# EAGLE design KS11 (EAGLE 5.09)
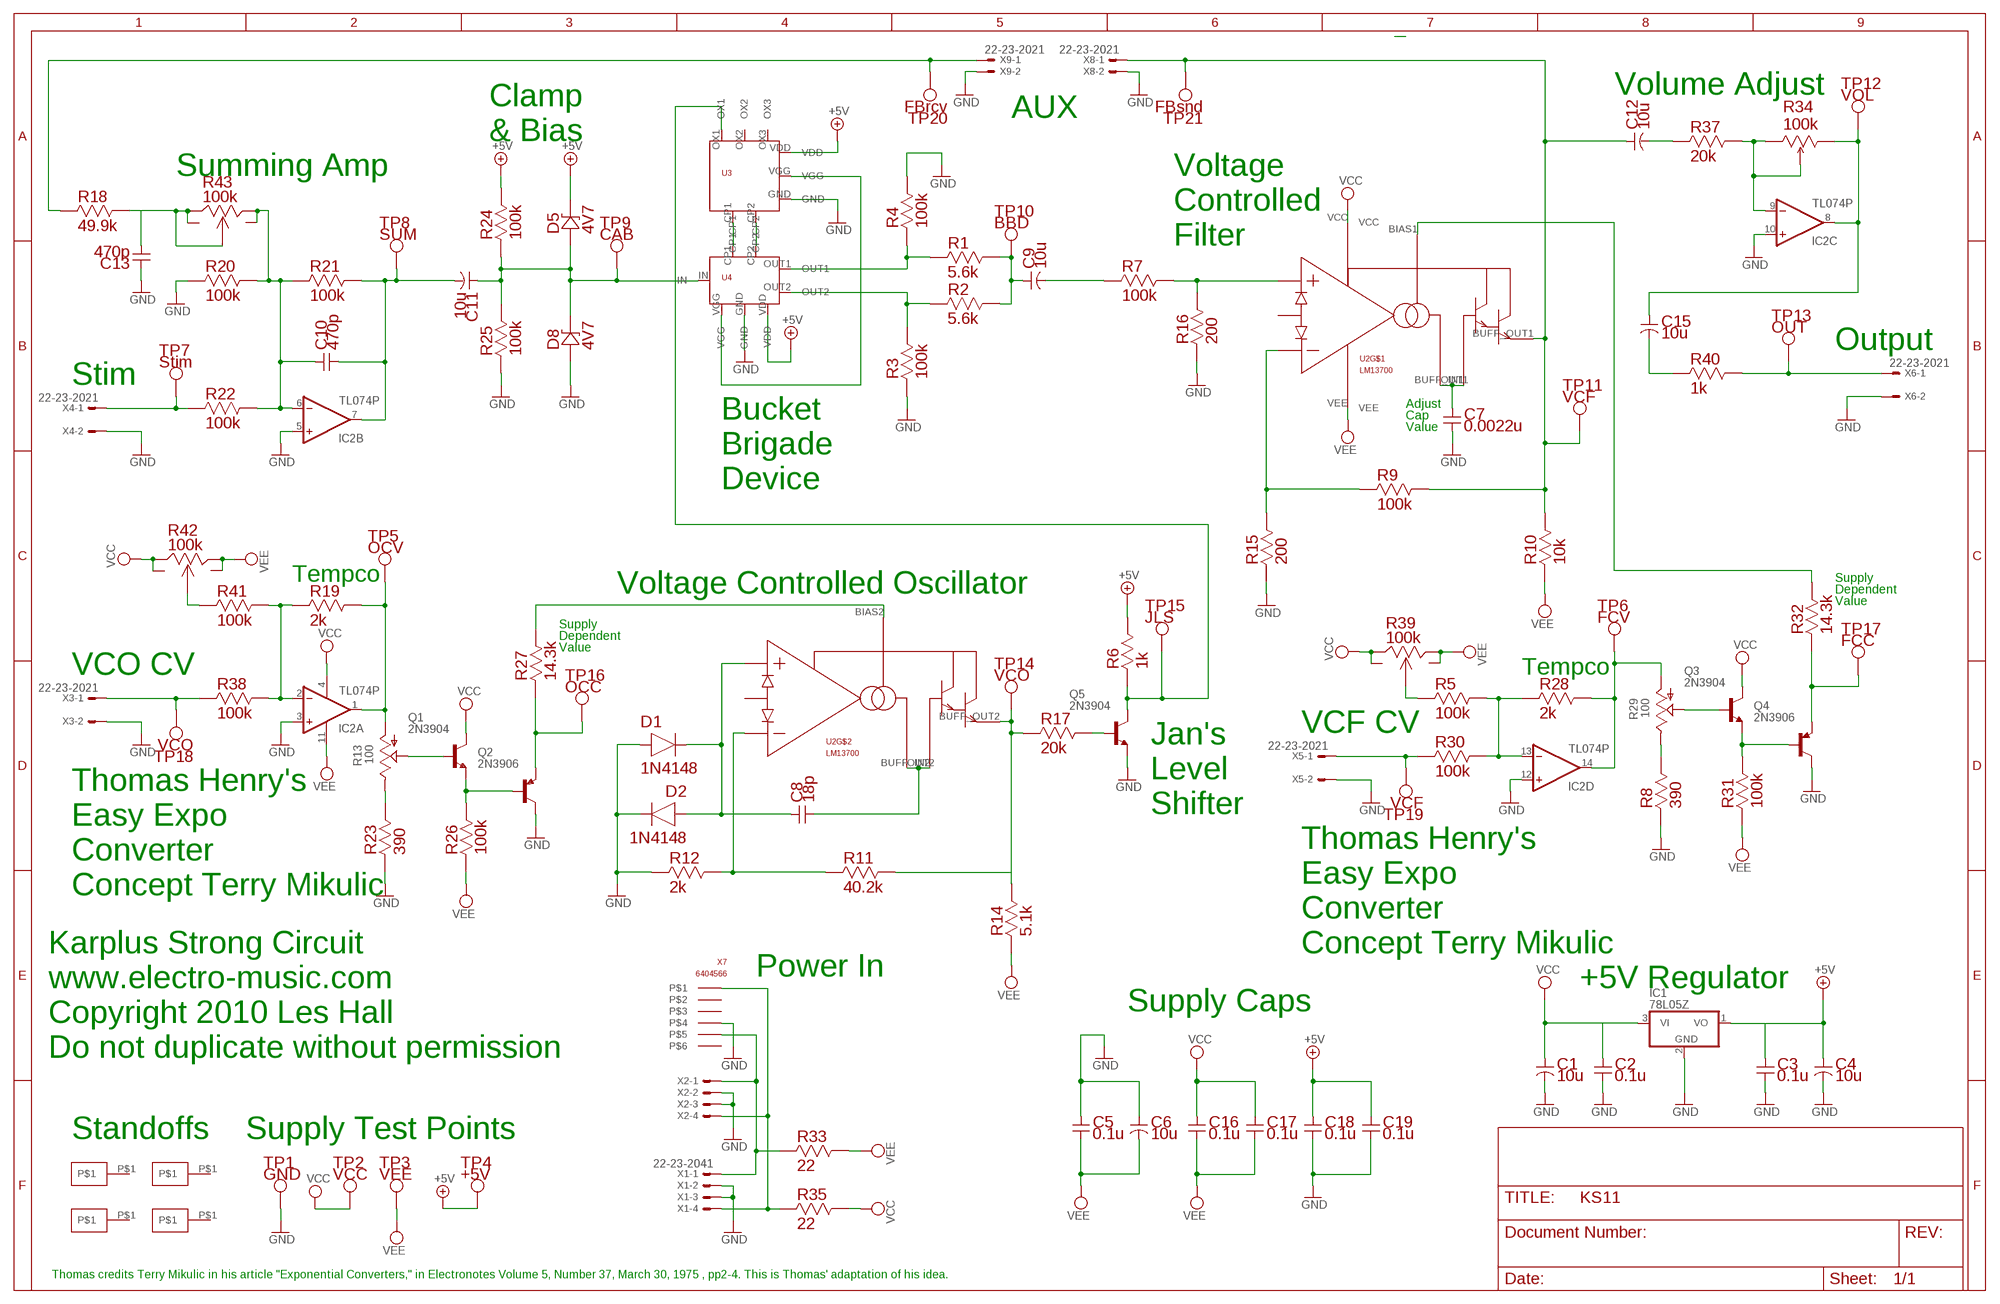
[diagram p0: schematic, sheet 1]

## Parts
C1  10u  ECAP100  [ECAP100]
C2  0.1u  CAP100  [CAP100]
C3  0.1u  CAP100  [CAP100]
C4  10u  ECAP100  [ECAP100]
C5  0.1u  CAP100  [CAP100]
C6  10u  ECAP100  [ECAP100]
C7  0.0022u  CAP100  [CAP100]
C8  18p  CAP100  [CAP100]
C9  10u  ECAP100  [ECAP100]
C10  470p  CAP100  [CAP100]
C11  10u  ECAP100  [ECAP100]
C12  10u  ECAP100  [ECAP100]
C13  470p  CAP100  [CAP100]
C15  10u  ECAP100  [ECAP100]
C16  0.1u  CAP100  [CAP100]
C17  0.1u  CAP100  [CAP100]
C18  0.1u  CAP100  [CAP100]
C19  0.1u  CAP100  [CAP100]
D1  1N4148  DIODE  [DIODE]
D2  1N4148  DIODE  [DIODE]
D5  4V7  ZENER  [ZENER]
D8  4V7  ZENER  [ZENER]
IC1  78L05Z  [TO92]
IC2  TL074P  [DIL14]
Q1  2N3904  [TO92]
Q2  2N3906  [TO92]
Q3  2N3904  [TO92]
Q4  2N3906  [TO92]
Q5  2N3904  [TO92]
R1  5.6k  RES400  [RES400]
R2  5.6k  RES400  [RES400]
R3  100k  RES400  [RES400]
R4  100k  RES400  [RES400]
R5  100k  RES400  [RES400]
R6  1k  RES400  [RES400]
R7  100k  RES400  [RES400]
R8  390  RES400  [RES400]
R9  100k  RES400  [RES400]
R10  10k  RES400  [RES400]
R11  40.2k  RES400  [RES400]
R12  2k  RES400  [RES400]
R13  100  TRIM_US-S64W  [S64W]
R14  5.1k  RES400  [RES400]
R15  200  RES400  [RES400]
R16  200  RES400  [RES400]
R17  20k  RES400  [RES400]
R18  49.9k  RES400  [RES400]
R19  2k  RES400  [RES400]
R20  100k  RES400  [RES400]
R21  100k  RES400  [RES400]
R22  100k  RES400  [RES400]
R23  390  RES400  [RES400]
R24  100k  RES400  [RES400]
R25  100k  RES400  [RES400]
R26  100k  RES400  [RES400]
R27  14.3k  RES400  [RES400]
R28  2k  RES400  [RES400]
R29  100  TRIM_US-S64W  [S64W]
R30  100k  RES400  [RES400]
R31  100k  RES400  [RES400]
R32  14.3k  RES400  [RES400]
R33  22  RES400  [RES400]
R34  100k  POTWHEEL  [POTWHEEL]
R35  22  RES400  [RES400]
R37  20k  RES400  [RES400]
R38  100k  RES400  [RES400]
R39  100k  POT2  [POT2]
R40  1k  RES400  [RES400]
R41  100k  RES400  [RES400]
R42  100k  POT2  [POT2]
R43  100k  POT2  [POT2]
S2  STANDOFF  [STANDOFF]
S3  STANDOFF  [STANDOFF]
S4  STANDOFF  [STANDOFF]
S5  STANDOFF  [STANDOFF]
TP1  GND  TESTPOINT  [TESTPOINT]
TP2  VCC  TESTPOINT  [TESTPOINT]
TP3  VEE  TESTPOINT  [TESTPOINT]
TP4  +5V  TESTPOINT  [TESTPOINT]
TP5  OCV  TESTPOINT  [TESTPOINT]
TP6  FCV  TESTPOINT  [TESTPOINT]
TP7  Stim  TESTPOINT  [TESTPOINT]
TP8  SUM  TESTPOINT  [TESTPOINT]
TP9  CAB  TESTPOINT  [TESTPOINT]
TP10  BBD  TESTPOINT  [TESTPOINT]
TP11  VCF  TESTPOINT  [TESTPOINT]
TP12  VOL  TESTPOINT  [TESTPOINT]
TP13  OUT  TESTPOINT  [TESTPOINT]
TP14  VCO  TESTPOINT  [TESTPOINT]
TP15  JLS  TESTPOINT  [TESTPOINT]
TP16  OCC  TESTPOINT  [TESTPOINT]
TP17  FCC  TESTPOINT  [TESTPOINT]
TP18  VCO  TESTPOINT  [TESTPOINT]
TP19  VCF  TESTPOINT  [TESTPOINT]
TP20  FBrcv  TESTPOINT  [TESTPOINT]
TP21  FBsnd  TESTPOINT  [TESTPOINT]
U2  LM13700  [LM13700]
U3  MN3102  [MN3102]
U4  MN3207  [MN3207]
X1  22-23-2041  [22-23-2041]
X2  KK-156-4  [KK-156-4]
X3  22-23-2021  [22-23-2021]
X4  22-23-2021  [22-23-2021]
X5  22-23-2021  [22-23-2021]
X6  22-23-2021  [22-23-2021]
X7  6404566  AMP6404566  [AMP6404566]
X8  22-23-2021  [22-23-2021]
X9  22-23-2021  [22-23-2021]

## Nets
+5V: C3.P$1 C4.P$1 C18.P$1 C19.P$1 D5.P$2 IC1.1(VO) R6.P$2 R24.P$2 TP4.P$1 U3.VDD U4.VDD
GND: C1.P$2 C2.P$2 C3.P$2 C4.P$2 C5.P$1 C6.P$1 C7.P$2 C13.P$1 C18.P$2 C19.P$2 D1.P$1 D2.P$2 D8.P$1 IC1.2(GND) IC2.3(A:+IN) IC2.5(B:+IN) IC2.10(C:+IN) IC2.12(D:+IN) Q2.1(C) Q4.1(C) Q5.3(E) R3.P$1 R4.P$2 R8.P$1 R12.P$1 R15.P$1 R16.P$1 R20.P$1 R23.P$1 R25.P$1 TP1.P$1 U3.GND U4.GND X1.2 X1.3 X2.2 X2.3 X3.2 X4.2 X5.2 X6.2 X7.P$4 X8.2 X9.2
N$1: R7.P$2 R16.P$2 U2.INPUT+1(INPUT+)
N$2: R9.P$1 R15.P$2 U2.INPUT-1(INPUT-)
N$3: C12.P$1 R9.P$2 R10.P$2 TP11.P$1 TP21.P$1 U2.BUFF_OUT1(BUFF_OUT) X8.1
N$4: C7.P$1 U2.BUFF_IN1(BUFF_IN) U2.OUT1(OUT)
N$5: IC2.14(D:OUT) R28.P$2 R29.A TP6.P$1
N$6: R5.P$1 R39.P$3
N$7: IC2.9(C:-IN) R34.P$1 R34.P$2 R37.P$2
N$8: C8.P$1 D1.P$2 D2.P$1 U2.INPUT+2(INPUT+)
N$9: R11.P$1 R12.P$2 U2.INPUT-2(INPUT-)
N$10: Q5.1(C) R6.P$1 TP15.P$1 U3.OX1
N$11: IC2.1(A:OUT) R13.A R19.P$2 TP5.P$1
N$12: R11.P$2 R14.P$2 R17.P$1 TP14.P$1 U2.BUFF_OUT2(BUFF_OUT)
N$13: C8.P$2 U2.BUFF_IN2(BUFF_IN) U2.OUT2(OUT)
N$14: U3.CP1 U4.CP1
N$15: U3.CP2 U4.CP2
N$16: C10.P$1 IC2.6(B:-IN) R20.P$2 R21.P$1 R22.P$2 R43.P$4 R43.P$5
N$17: U3.VGG U4.VGG
N$18: C10.P$2 C11.P$2 IC2.7(B:OUT) R21.P$2 TP8.P$1
N$19: R1.P$1 R4.P$1 U4.OUT1
N$20: C15.P$2 R40.P$1
N$21: R2.P$1 R3.P$2 U4.OUT2
N$22: C13.P$2 R18.P$2 R43.P$1 R43.P$2 R43.P$3
N$23: C9.P$1 R1.P$2 R2.P$2 TP10.P$1
N$24: Q5.2(B) R17.P$2
N$25: R41.P$1 R42.P$3
N$26: C9.P$2 R7.P$1
N$27: R22.P$1 TP7.P$1 X4.1
N$28: C11.P$1 D5.P$1 D8.P$2 R24.P$1 R25.P$2 TP9.P$1 U4.IN
N$29: R27.P$2 U2.BIAS2(BIAS)
N$30: R32.P$2 U2.BIAS1(BIAS)
N$31: IC2.13(D:-IN) R5.P$2 R28.P$1 R30.P$2
N$32: R30.P$1 TP19.P$1 X5.1
N$34: R40.P$2 TP13.P$1 X6.1
N$35: R18.P$1 TP20.P$1 X9.1
N$37: C15.P$1 IC2.8(C:OUT) R34.P$3 TP12.P$1
N$38: IC2.2(A:-IN) R19.P$1 R38.P$2 R41.P$2
N$40: C12.P$2 R37.P$1
N$45: Q1.2(B) R13.S
N$46: R13.E R23.P$2
N$47: Q1.3(E) Q2.2(B) R26.P$2
N$48: R38.P$1 TP18.P$1 X3.1
N$49: Q2.3(E) R27.P$1 TP16.P$1
N$50: R33.P$1 X1.1 X2.1 X7.P$5
N$51: Q3.3(E) Q4.2(B) R31.P$2
N$52: Q4.3(E) R32.P$1 TP17.P$1
N$53: Q3.2(B) R29.S
N$54: R8.P$2 R29.E
N$56: R35.P$1 X1.4 X2.4 X7.P$1
VCC: C1.P$1 C2.P$1 C16.P$1 C17.P$1 IC1.3(VI) IC2.4(P:V+) Q1.1(C) Q3.1(C) R35.P$2 R39.P$1 R39.P$2 R42.P$1 R42.P$2 TP2.P$1 U2.VCC
VEE: C5.P$2 C6.P$2 C16.P$2 C17.P$2 IC2.11(P:V-) R10.P$1 R14.P$1 R26.P$1 R31.P$1 R33.P$2 R39.P$4 R39.P$5 R42.P$4 R42.P$5 TP3.P$1 U2.VEE
Unconnected: S2.P$1 S3.P$1 S4.P$1 S5.P$1 U2.DIODE_BIAS1(DIODE_BIAS) U2.DIODE_BIAS2(DIODE_BIAS) U3.OX2 U3.OX3 X7.P$2 X7.P$3 X7.P$6

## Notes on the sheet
- Volume Adjust
- Clamp
- AUX
- & Bias
- Summing Amp | Voltage
- Controlled
- Filter
- Output
- Stim
- Adjust
- Bucket | Cap
- Value
- Brigade
- Device
- Tempco | Supply
- Voltage Controlled Oscillator | Dependent
- Value
- Supply
- Dependent
- Value
- VCO CV | Tempco
- VCF CV
- Jan's
- Level
- Thomas Henry's
- Shifter
- Easy Expo
- Thomas Henry's
- Converter
- Easy Expo
- Concept Terry Mikulic
- Converter
- Karplus Strong Circuit | Concept Terry Mikulic
- Power In
- www.electro-music.com | +5V Regulator
- Supply Caps
- Copyright 2010 Les Hall
- Do not duplicate without permission
- Standoffs | Supply Test Points
- Thomas credits Terry Mikulic in his article "Exponential Converters," in Electronotes Volume 5, Number 37, March 30, 1975 , pp2-4. This is Thomas' adaptation of his idea.

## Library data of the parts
C1 C4 C6 C9 C11 C12 C15 = eChucK:ECAP100
C2 C3 C5 C7 C8 C10 C13 C16-C19 = eChucK:CAP100
D1 D2 = eChucK:DIODE
D5 D8 = eChucK:ZENER
IC1 = linear:78*: Positive VOLTAGE REGULATOR Source: http://cache.national.com/ds/LM/LM78L05.pdf http://www.fairchildsemi.com/ds/LM/LM7805.pdf
IC2 = linear:TL074: OP AMP
Q1 Q3 Q5 = eChucK:2N3904: NPN Transistor
Q2 Q4 = eChucK:2N3906: PNP Transistor
R1-R12 R14-R28 R30-R33 R35 R37 R38 R40 R41 = KarplusStrong:RES400
R13 R29 = pot:TRIM_US-: POTENTIOMETER
R34 = eChucK:POTWHEEL
R39 R42 R43 = eChucK:POT2: double footprinted potentiometer
S2-S5 = eChucK:STANDOFF
TP1-TP21 = eChucK:TESTPOINT
U2 = eChucK:LM13700: LM13700 Variable Gain Amplifier
U3 = eChucK:MN3102: MN3102 Clock / Driver
U4 = eChucK:MN3207: MN3207 1024 Stage Bucket Brigade Device
X1 = con-molex:22-23-2041: .100" (2.54mm) Center Header - 4 Pin
X2 = con-molex:KK-156-4: KK 156 HEADER Source: http://www.molex.com/pdm_docs/sd/026604100_sd.pdf
X3-X6 X8 X9 = eChucK:22-23-2021: .100" (2.54mm) Center Header - 2 Pin
X7 = eChucK:AMP6404566: AMP 6404566 power supply connector

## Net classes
0 default: width 0.762 mm, drill 0.508 mm, clearance 0.254 mm

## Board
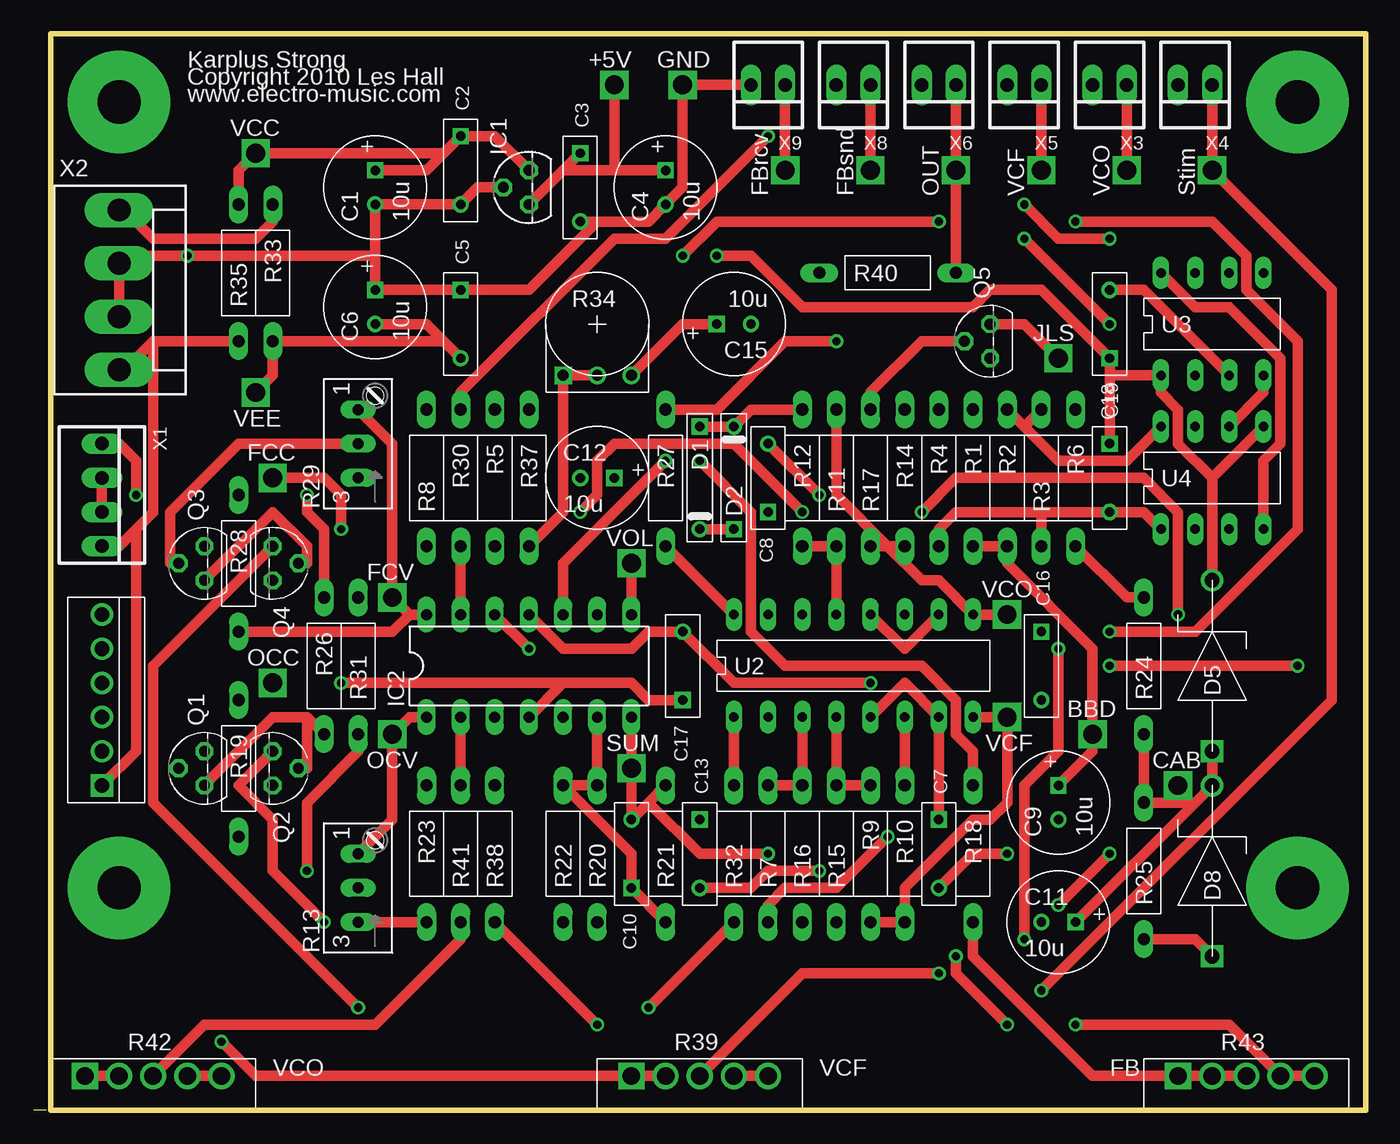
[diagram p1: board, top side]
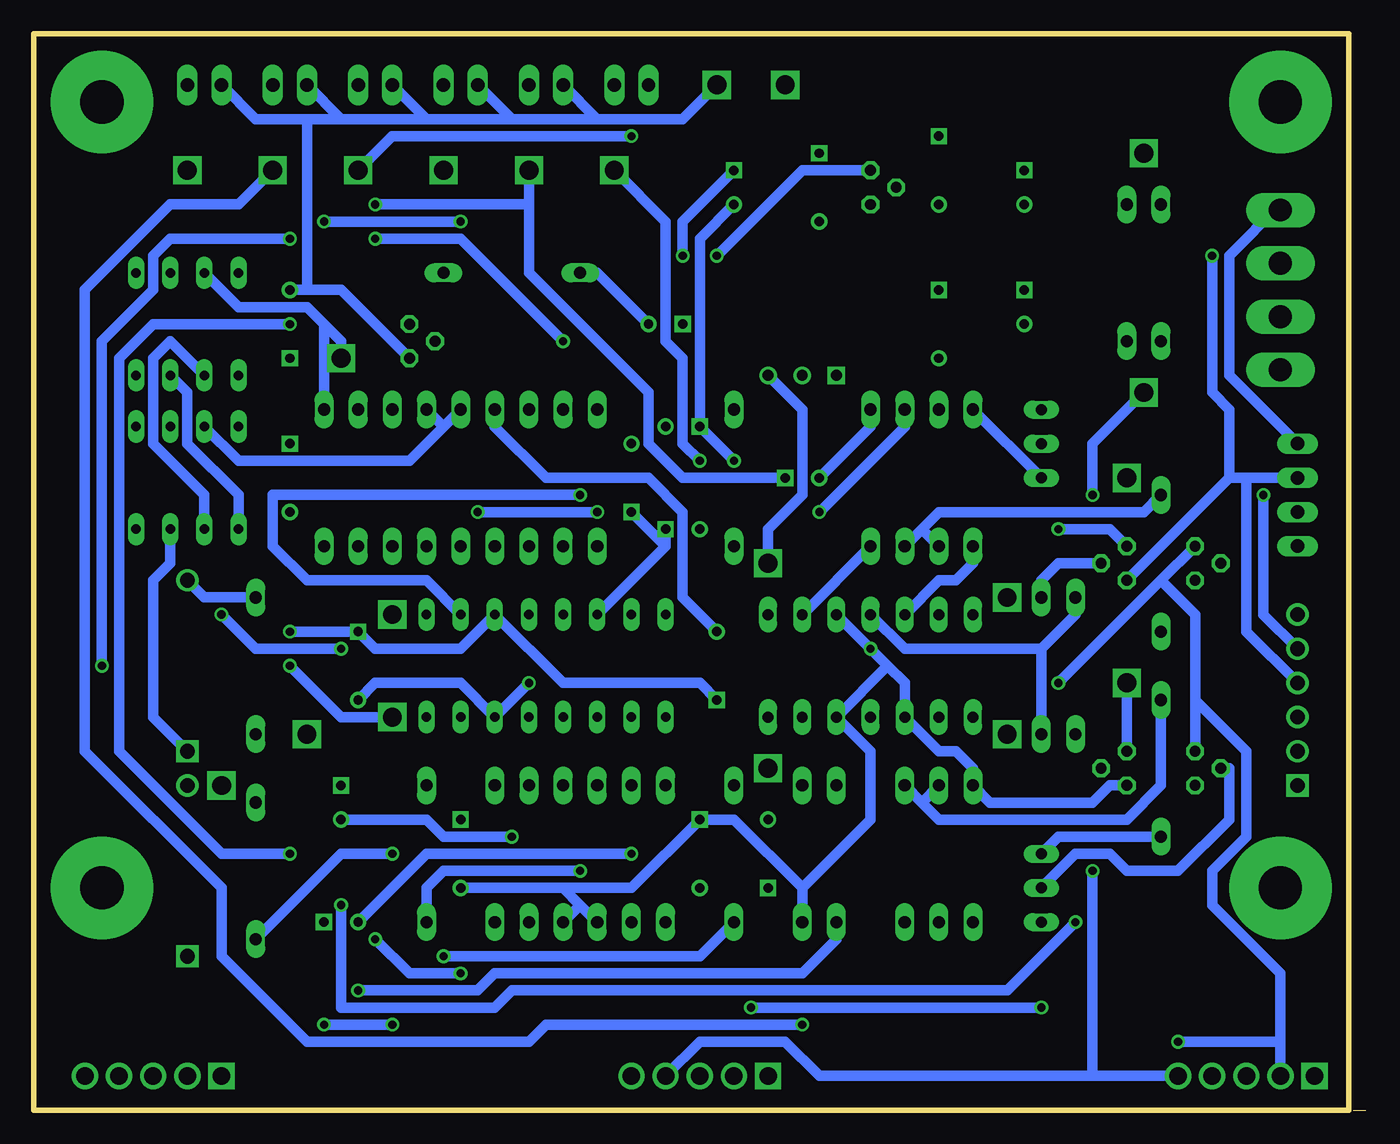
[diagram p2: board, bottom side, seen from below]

Size 99.06 x 80.02 mm. Coordinates in mm from the lower left corner, seen from the top.
Outline: 0.94,0 0,0
Outline: 1.27,0.01 1.27,80.02 99.06,80.02 99.06,0.01 1.27,0.01
Copper layers (1*16): Top 0.035mm / dielectric 1.5mm / Bottom 0.035mm
Design rules "default": minimum track width 10mil, minimum drill 24mil, track to track 8mil, track to pad 8mil, pad to pad 8mil, via to via 8mil, smd to smd 8mil, copper to edge 40mil, drill to drill 8mil, minimum pad ring 10mil, minimum via ring 8mil, stop-mask expansion 4mil, vias tented up to drill 0mil, thermal gap 10mil

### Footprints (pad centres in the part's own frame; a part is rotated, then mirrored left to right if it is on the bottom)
ECAP100 = drill 0.7 square: P$1 1.27,0 | drill 0.7 round: P$2 -1.27,0
CAP100 = drill 0.7 square: P$1 2.54,0 | drill 0.7 round: P$2 -2.54,0
DIODE = drill 0.7 square: P$1 -3.81,0 | drill 0.7 round: P$2 3.81,0
ZENER = drill 1.1 square: P$1 -6.35,0 | drill 1.1 round: P$2 6.35,0
TO92 = drill 0.813 octagon: 1 -1.27,0; 2 0,1.905; 3 1.27,0
DIL14 = drill 0.813 long: 1 -7.62,-3.81; 2 -5.08,-3.81; 3 -2.54,-3.81; 4 0,-3.81; 5 2.54,-3.81; 6 5.08,-3.81; 7 7.62,-3.81; 8 7.62,3.81; 9 5.08,3.81; 10 2.54,3.81; 11 0,3.81; 12 -2.54,3.81; 13 -5.08,3.81; 14 -7.62,3.81
TO92' = drill 0.813 octagon: 1 1.27,0; 2 0,1.905; 3 -1.27,0
RES400 = drill 0.9 long: P$1 -5.08,0; P$2 5.08,0
S64W = drill 0.813 long: A 2.54,1.27; E -2.54,1.27; S 0,1.27
POTWHEEL = drill 0.8 square: P$1 -2.54,0 | drill 0.8 round: P$2 0,0; P$3 2.54,0
POT2 = drill 1.3 square: P$1 -5.08,0 | drill 1.3 round: P$2 -2.54,0; P$3 0,0; P$4 2.54,0; P$5 5.08,0
STANDOFF = drill 3.2 pad 7.62 round: P$1 0,0
TESTPOINT = drill 1.4 square: P$1 0,0
LM13700 = drill 0.7 long: BIAS1 -8.89,-3.81; BIAS2 -8.89,3.81; BUFF_IN1 6.35,-3.81; BUFF_IN2 6.35,3.81; BUFF_OUT1 8.89,-3.81; BUFF_OUT2 8.89,3.81; DIODE_BIAS1 -6.35,-3.81; DIODE_BIAS2 -6.35,3.81; INPUT+1 -3.81,-3.81; INPUT+2 -3.81,3.81; INPUT-1 -1.27,-3.81; INPUT-2 -1.27,3.81; OUT1 1.27,-3.81; OUT2 1.27,3.81; VCC 3.81,3.81; VEE 3.81,-3.81
MN3102 = drill 0.7 long: CP1 -1.27,-3.81; CP2 3.81,-3.81; GND 1.27,-3.81; OX1 -1.27,3.81; OX2 1.27,3.81; OX3 3.81,3.81; VDD -3.81,-3.81; VGG -3.81,3.81
MN3207 = drill 0.7 long: CP1 -1.27,-3.81; CP2 1.27,3.81; GND -3.81,-3.81; IN 1.27,-3.81; OUT1 -1.27,3.81; OUT2 -3.81,3.81; VDD 3.81,3.81; VGG 3.81,-3.81
22-23-2041 = drill 1 long: 1 -3.81,0; 2 -1.27,0; 3 1.27,0; 4 3.81,0
KK-156-4 = drill 1.7 pad 2.184 long: 1 -5.94,0; 2 -1.98,0; 3 1.98,0; 4 5.94,0
22-23-2021 = drill 1 long: 1 -1.27,0; 2 1.27,0
AMP6404566 = drill 1.1 square: P$1 6.35,0 | drill 1.1 round: P$2 3.81,0; P$3 1.27,0; P$4 -1.27,0; P$5 -3.81,0; P$6 -6.35,0

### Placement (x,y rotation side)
C1  25.4,68.59 90 top
C2  31.75,69.86 90 top
C3  40.64,68.59 90 top
C4  46.99,68.59 90 top
C5  31.75,58.43 90 top
C6  25.4,59.7 90 top
C7  67.31,19.06 90 top
C8  54.61,47 270 top
C9  76.2,22.87 90 top
C10  44.45,19.06 270 top
C11  76.2,13.98 0 top
C12  41.91,47 0 top
C13  49.53,19.06 90 top
C15  52.07,58.43 180 top
C16  74.93,33.03 90 top
C17  48.26,33.03 270 top
C18  80.01,58.43 270 top
C19  80.01,47 90 top
D1  49.53,47 270 top
D2  52.07,47 90 top
D5  87.63,33.03 90 top
D8  87.63,17.79 90 top
IC1  36.83,68.59 90 top
IC2  36.83,33.03 0 top
Q1  2N3904  [TO92']  12.7,25.41 90 top
Q2  2N3906  [TO92']  17.78,25.41 270 top
Q3  2N3904  [TO92']  12.7,40.65 90 top
Q4  2N3906  [TO92']  17.78,40.65 270 top
Q5  2N3904  [TO92']  71.12,57.16 90 top
R1  69.85,47 270 top
R2  72.39,47 270 top
R3  74.93,47 90 top
R4  67.31,47 270 top
R5  34.29,47 270 top
R6  77.47,47 270 top
R7  54.61,19.06 90 top
R8  29.21,47 90 top
R9  62.23,19.06 270 top
R10  64.77,19.06 270 top
R11  59.69,47 90 top
R12  57.15,47 270 top
R13  25.4,16.52 90 top
R14  64.77,47 270 top
R15  59.69,19.06 90 top
R16  57.15,19.06 90 top
R17  62.23,47 90 top
R18  69.85,19.06 270 top
R19  15.24,25.41 270 top
R20  41.91,19.06 90 top
R21  46.99,19.06 90 top
R22  39.37,19.06 90 top
R23  29.21,19.06 270 top
R24  82.55,33.03 90 top
R25  82.55,17.79 90 top
R26  21.59,33.03 270 top
R27  46.99,47 270 top
R28  15.24,40.65 270 top
R29  25.4,49.54 90 top
R30  31.75,47 270 top
R31  24.13,33.03 90 top
R32  52.07,19.06 90 top
R33  17.78,62.24 270 top
R34  41.91,54.62 0 top
R35  15.24,62.24 90 top
R37  36.83,47 270 top
R38  34.29,19.06 90 top
R39  49.53,2.55 0 top
R40  63.5,62.24 0 top
R41  31.75,19.06 90 top
R42  8.89,2.55 0 top
R43  90.17,2.55 0 top
S2  6.35,16.52 0 top
S3  6.35,74.94 0 top
S4  93.98,74.94 0 top
S5  93.98,16.52 0 top
TP1  48.26,76.21 0 top
TP2  16.51,71.13 0 top
TP3  16.51,53.35 180 top
TP4  43.18,76.21 0 top
TP5  26.67,27.95 180 top
TP6  26.67,38.11 0 top
TP7  87.63,69.86 90 top
TP8  44.45,25.41 0 top
TP9  85.09,24.14 0 top
TP10  78.74,27.95 0 top
TP11  72.39,29.22 180 top
TP12  44.45,40.65 0 top
TP13  68.58,69.86 90 top
TP14  72.39,36.84 0 top
TP15  76.2,55.89 0 top
TP16  17.78,31.76 0 top
TP17  17.78,47 0 top
TP18  81.28,69.86 90 top
TP19  74.93,69.86 90 top
TP20  55.88,69.86 90 top
TP21  62.23,69.86 90 top
U2  60.96,33.03 0 top
U3  87.63,58.43 0 top
U4  87.63,47 0 top
X1  5.08,45.73 270 top
X2  6.35,60.97 270 top
X3  80.01,76.21 180 top
X4  86.36,76.21 180 top
X5  73.66,76.21 180 top
X6  67.31,76.21 180 top
X7  5.08,30.49 270 top
X8  60.96,76.21 180 top
X9  54.61,76.21 180 top

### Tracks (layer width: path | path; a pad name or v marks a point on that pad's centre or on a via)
+5V  (via drill 0.61)
  Top 0.762: IC1.1 39.37,69.86 | 39.37,69.86 C3.P$1 | 39.37,69.86 43.18,69.86 | 43.18,69.86 C4.P$1 | 43.18,69.86 TP4.P$1 | 80.01,54.62 C18.P$1 74.93,60.97 71.12,60.97 69.85,59.7 57.15,59.7 53.34,63.51 v50.8,63.51 | 80.01,54.62 C19.P$1 | 80.01,54.62 U3.VDD 83.82,53.35 85.09,52.08 85.09,49.54 87.63,47 | 87.63,47 U4.VDD | 87.63,47 D5.P$2 | R6.P$2 81.28,38.11 R24.P$2
  Bottom 0.762: R24.P$2 86.36,38.11 D5.P$2 | C4.P$1 50.8,66.05 v50.8,63.51
GND  (via drill 0.61)
  Top 0.762: v36.83,34.3 IC2.12 | R25.P$1 86.36,12.71 D8.P$1 | v72.39,19.06 69.85,19.06 C7.P$2 | X1.2 X1.3 | X2.3 X2.2 6.35,63.51 v11.43,63.51 25.4,63.51 | 25.4,63.51 C1.P$2 C2.P$2 33.02,68.59 IC1.2 | 25.4,63.51 C6.P$1 C5.P$1 36.83,60.97 41.91,66.05 | U4.GND 82.55,44.46 C19.P$2 74.93,44.46 | R4.P$2 67.31,43.19 68.58,44.46 74.93,44.46 | 74.93,44.46 R3.P$1 | U3.GND 82.55,60.97 C18.P$2 | D1.P$1 D2.P$2 53.34,52.08 R12.P$1 | 41.91,66.05 45.72,66.05 C4.P$2 48.26,68.59 TP1.P$1 X9.2 | 41.91,66.05 C3.P$2 | IC2.10 39.37,40.65 v46.99,48.27
  Bottom 0.762: Q2.1 19.05,24.14 20.32,22.87 27.94,22.87 R23.P$1 29.21,25.41 30.48,26.68 31.75,26.68 IC2.3 34.29,31.76 35.56,33.03 | IC2.10 v36.83,34.3 35.56,33.03 | 35.56,33.03 IC2.5 36.83,26.68 36.83,21.6 41.91,16.52 | R8.P$1 29.21,40.65 30.48,39.38 31.75,39.38 IC2.12 | 41.91,16.52 46.99,21.6 C13.P$1 54.61,16.52 59.69,16.52 | 41.91,16.52 R20.P$1 | 59.69,16.52 C7.P$2 | 58.42,15.25 R16.P$1 | 59.69,16.52 58.42,15.25 | 58.42,15.25 R15.P$1 | R25.P$1 76.2,19.06 v72.39,19.06 | 10.16,47 Q4.1 | 8.89,47 X1.2 | 8.89,47 10.16,47 | X7.P$4 8.89,35.57 8.89,47 | 10.16,47 10.16,52.08 11.43,53.35 v11.43,63.51 | 78.74,60.97 76.2,60.97 Q5.3 | 78.74,60.97 C18.P$2 | U4.GND 83.82,45.73 87.63,49.54 87.63,53.35 U3.GND | 57.15,73.67 X8.2 | 57.15,73.67 50.8,73.67 TP1.P$1 | 63.5,73.67 X6.2 | 57.15,73.67 63.5,73.67 | 69.85,73.67 X5.2 | 63.5,73.67 69.85,73.67 | 76.2,73.67 X3.2 | 69.85,73.67 76.2,73.67 | X4.2 82.55,73.67 78.74,73.67 | 76.2,73.67 78.74,73.67 | C4.P$2 49.53,64.78 D1.P$1 v46.99,48.27 | 78.74,73.67 78.74,60.97
N$1
  Top 0.762: U2.INPUT+1 R16.P$2 R7.P$2
N$2
  Top 0.762: U2.INPUT-1 R15.P$2 R9.P$1
N$3  (via drill 0.61)
  Top 0.762: R9.P$2 R10.P$2 64.77,16.52 69.85,21.6 71.12,21.6 72.39,22.87 TP11.P$1 U2.BUFF_OUT1 | TP21.P$1 X8.1 | v80.01,33.03 v93.98,33.03 | v80.01,64.78 76.2,64.78 v73.66,67.32
  Bottom 0.762: C12.P$1 50.8,47 53.34,49.54 53.34,53.35 62.23,62.24 62.23,67.32 | 62.23,67.32 TP21.P$1 | TP11.P$1 76.2,29.22 v80.01,33.03 | v93.98,33.03 93.98,57.16 90.17,60.97 90.17,63.51 88.9,64.78 v80.01,64.78 | v73.66,67.32 62.23,67.32
N$4
  Top 0.762: C7.P$1 U2.BUFF_IN1 64.77,31.76 U2.OUT1
N$5
  Top 0.762: 27.94,36.84 IC2.14 | 27.94,36.84 TP6.P$1 26.67,49.54 R29.A | R28.P$2 26.67,35.57 27.94,36.84
N$6  (via drill 0.61)
  Top 0.762: v40.64,44.46 41.91,45.73 41.91,48.27 43.18,49.54 52.07,49.54 v57.15,44.46 | v66.04,44.46 68.58,47 82.55,47 85.09,44.46 v85.09,36.84 | v76.2,34.3 76.2,26.68 73.66,24.14 v73.66,12.71 | v67.31,10.17 57.15,10.17 R39.P$3
  Bottom 0.762: R5.P$1 34.29,50.81 v40.64,44.46 | v66.04,44.46 v57.15,44.46 | v85.09,36.84 82.55,34.3 v76.2,34.3 | v73.66,12.71 71.12,10.17 v67.31,10.17
N$7
  Top 0.762: R34.P$2 R34.P$1 39.37,44.46 R37.P$2
  Bottom 0.762: IC2.9 R37.P$2
N$8
  Top 0.762: D2.P$1 D1.P$2
  Bottom 0.762: U2.INPUT+2 52.07,41.92 | 52.07,41.92 D2.P$1 | 52.07,41.92 C8.P$1
N$9
  Top 0.762: U2.INPUT-2 R11.P$1 R12.P$2
N$10
  Top 0.762: Q5.1 73.66,58.43 TP15.P$1
  Bottom 0.762: U3.OX1 83.82,59.7 78.74,59.7 77.47,58.43 | 77.47,58.43 76.2,57.16 TP15.P$1 | 77.47,58.43 R6.P$1
N$11
  Top 0.762: IC2.1 27.94,29.22 TP5.P$1 26.67,21.6 R13.A
  Bottom 0.762: R13.A 22.86,20.33 R19.P$2
N$12
  Top 0.762: TP14.P$1 U2.BUFF_OUT2 67.31,39.38 66.04,39.38 63.5,41.92 | 63.5,41.92 R14.P$2 | R17.P$1 63.5,41.92 | R11.P$2 59.69,45.73 63.5,41.92
N$13  (via drill 0.61)
  Top 0.762: U2.OUT2 64.77,34.3 U2.BUFF_IN2 | v58.42,45.73 C8.P$2
  Bottom 0.762: v58.42,45.73 81.28,45.73 81.28,41.92 78.74,39.38 69.85,39.38 U2.BUFF_IN2
N$14
  Bottom 0.762: U4.CP1 86.36,45.73 90.17,49.54 90.17,55.89 88.9,57.16 U3.CP1
N$15
  Top 0.762: U4.CP2 91.44,53.35 U3.CP2
N$16  (via drill 0.61)
  Top 0.762: R43.P$5 R43.P$4 88.9,6.36 v77.47,6.36 | R21.P$1 C10.P$1 44.45,19.06 R22.P$2 R20.P$2 IC2.6 | v72.39,6.36 68.58,10.17 v68.58,11.44
  Bottom 0.762: v72.39,6.36 v77.47,6.36 | v68.58,11.44 49.53,11.44 R21.P$1
N$17
  Top 0.762: U4.VGG 91.44,48.27 92.71,49.54 92.71,55.89 88.9,59.7 86.36,59.7 U3.VGG
N$18  (via drill 0.61)
  Top 0.762: IC2.7 TP8.P$1 C10.P$2 45.72,22.87 | 45.72,22.87 R21.P$2 | v54.61,19.06 49.53,19.06 45.72,22.87
  Bottom 0.762: C11.P$2 69.85,19.06 v54.61,19.06
N$19
  Bottom 0.762: U4.OUT1 83.82,48.27 71.12,48.27 68.58,50.81 | R4.P$1 68.58,50.81 | 68.58,50.81 R1.P$1
N$20
  Bottom 0.762: C15.P$2 57.15,62.24 R40.P$1
N$21
  Top 0.762: U4.OUT2 81.28,48.27 76.2,48.27 73.66,50.81 | R2.P$1 73.66,50.81 | 73.66,50.81 R3.P$2
N$22  (via drill 0.61)
  Top 0.762: R43.P$3 R43.P$2 R43.P$1 78.74,2.55 69.85,11.44 R18.P$2 | C13.P$2 53.34,16.52 54.61,17.79 v58.42,17.79
  Bottom 0.762: v58.42,17.79 68.58,17.79 69.85,16.52 R18.P$2
N$23
  Top 0.762: R1.P$2 R2.P$2 72.39,40.65 78.74,34.3 TP10.P$1 78.74,26.68 C9.P$1
N$24
  Top 0.762: R17.P$2 62.23,53.35 66.04,57.16 Q5.2
N$25
  Top 0.762: R41.P$1 31.75,12.71 25.4,6.36 12.7,6.36 R42.P$3
N$26  (via drill 0.61)
  Top 0.762: v63.5,20.33 59.69,16.52 55.88,16.52 54.61,15.25 R7.P$1
  Bottom 0.762: C9.P$2 69.85,21.6 68.58,20.33 v63.5,20.33
N$27  (via drill 0.61)
  Top 0.762: v74.93,8.9 96.52,30.49 96.52,60.97 TP7.P$1 X4.1
  Bottom 0.762: R22.P$1 39.37,12.71 41.91,10.17 64.77,10.17 66.04,8.9 v74.93,8.9
N$28
  Top 0.762: 86.36,22.87 D8.P$2 D5.P$1 | C11.P$1 86.36,22.87 | 86.36,22.87 85.09,22.87 | 85.09,22.87 R25.P$2 R24.P$1 | 85.09,22.87 TP9.P$1
  Bottom 0.762: U4.IN 88.9,40.65 90.17,39.38 90.17,29.22 D5.P$1
N$29
  Top 0.762: R27.P$2 U2.BIAS2
N$30
  Top 0.762: R32.P$2 U2.BIAS1
N$31
  Top 0.762: R30.P$2 IC2.13
  Bottom 0.762: R28.P$1 16.51,44.46 31.75,44.46 33.02,43.19 | 33.02,43.19 R5.P$2 | 33.02,43.19 R30.P$2
N$32  (via drill 0.61)
  Top 0.762: R30.P$1 31.75,53.35 43.18,64.78 46.99,64.78 v54.61,72.4 | TP19.P$1 X5.1
  Bottom 0.762: v54.61,72.4 72.39,72.4 TP19.P$1
N$34
  Top 0.762: R40.P$2 TP13.P$1 X6.1
N$35  (via drill 0.61)
  Top 0.762: R18.P$1 69.85,26.68 68.58,27.95 68.58,30.49 66.04,33.03 55.88,33.03 53.34,35.57 53.34,44.46 v49.53,48.27 | TP20.P$1 X9.1
  Bottom 0.762: v49.53,48.27 50.8,49.54 50.8,55.89 52.07,57.16 52.07,66.05 TP20.P$1
N$37
  Top 0.762: IC2.8 TP12.P$1 | C15.P$1 48.26,58.43 R34.P$3
  Bottom 0.762: TP12.P$1 44.45,43.19 41.91,45.73 41.91,52.08 R34.P$3
N$38
  Top 0.762: R41.P$2 IC2.2
  Bottom 0.762: R19.P$1 15.24,24.14 17.78,21.6 31.75,21.6 33.02,22.87 | 33.02,22.87 R38.P$2 | 33.02,22.87 R41.P$2
N$40
  Bottom 0.762: C12.P$2 36.83,50.81 R37.P$1
N$45
  Bottom 0.762: R13.S 21.59,19.06 19.05,19.06 17.78,17.79 13.97,17.79 10.16,21.6 10.16,25.41 Q1.2
N$46
  Top 0.762: R13.E R23.P$2
N$47
  Top 0.762: Q1.3 17.78,29.22 20.32,29.22 | 20.32,29.22 R26.P$2 | 20.32,29.22 20.32,25.41 Q2.2
N$48  (via drill 0.61)
  Top 0.762: R38.P$1 v41.91,6.36 | TP18.P$1 X3.1
  Bottom 0.762: v41.91,6.36 60.96,6.36 62.23,5.09 78.74,5.09 85.09,11.44 85.09,16.52 95.25,26.68 95.25,60.97 88.9,67.32 83.82,67.32 TP18.P$1
N$49  (via drill 0.61)
  Top 0.762: R27.P$1 50.8,52.08 55.88,57.16 v59.69,57.16 | v80.01,58.43 v73.66,64.78 | v76.2,15.25 v80.01,19.06 | v21.59,13.98 17.78,17.79 17.78,21.6 15.24,24.14 Q2.3
  Bottom 0.762: Q2.3 TP16.P$1 | v59.69,57.16 67.31,64.78 v73.66,64.78 | v80.01,58.43 90.17,58.43 92.71,55.89 92.71,26.68 85.09,19.06 v80.01,19.06 | v76.2,15.25 76.2,7.63 64.77,7.63 63.5,8.9 26.67,8.9 v21.59,13.98
N$50  (via drill 0.61)
  Top 0.762: R33.P$1 17.78,66.05 16.51,64.78 8.89,64.78 6.35,67.32 X2.1 | v7.62,45.73 7.62,48.27 6.35,49.54 X1.1
  Bottom 0.762: X1.1 10.16,54.62 10.16,63.51 6.35,67.32 X2.1 | X7.P$5 7.62,36.84 v7.62,45.73
N$51
  Top 0.762: Q3.3 17.78,44.46 20.32,41.92 20.32,40.65 Q4.2
  Bottom 0.762: R31.P$2 24.13,39.38 22.86,40.65 Q4.2
N$52  (via drill 0.61)
  Top 0.762: v22.86,43.19 22.86,45.73 21.59,47 TP17.P$1 | v45.72,7.63 R32.P$1 | v24.13,7.63 8.89,22.87 8.89,33.03 Q4.3
  Bottom 0.762: Q4.3 19.05,43.19 v22.86,43.19 | v24.13,7.63 v45.72,7.63
N$53
  Top 0.762: R29.S 15.24,49.54 10.16,44.46 10.16,40.65 Q3.2
N$54
  Bottom 0.762: R29.E R8.P$2
N$56
  Top 0.762: 8.89,57.16 R35.P$1 | 8.89,57.16 6.35,54.62 X2.4 | X1.4 6.35,41.92 7.62,43.19 | 7.62,43.19 8.89,44.46 8.89,57.16 | X7.P$1 7.62,26.68 7.62,43.19
VCC  (via drill 0.61)
  Top 0.762: R39.P$2 R39.P$1 16.51,2.55 v13.97,5.09 | R42.P$1 R42.P$2 | R35.P$2 15.24,69.86 TP2.P$1 30.48,71.13 | C1.P$1 29.21,69.86 30.48,71.13 | 30.48,71.13 C2.P$1 34.29,72.4 IC1.3 | C17.P$1 45.72,30.49 44.45,31.76 39.37,31.76 | 39.37,31.76 IC2.4 | v48.26,63.51 50.8,66.05 v67.31,66.05 | v77.47,66.05 87.63,66.05 90.17,63.51 90.17,60.97 93.98,57.16 93.98,43.19 86.36,35.57 v80.01,35.57 | v22.86,31.76 39.37,31.76
  Bottom 0.762: 12.7,30.49 12.7,36.84 15.24,39.38 | 12.7,30.49 Q1.1 | 15.24,39.38 Q3.1 | 6.35,5.09 6.35,10.17 11.43,15.25 11.43,17.79 8.89,20.33 8.89,26.68 12.7,30.49 | R42.P$2 6.35,5.09 | 6.35,5.09 v13.97,5.09 | C17.P$1 49.53,31.76 59.69,31.76 U2.VCC 67.31,34.3 73.66,34.3 C16.P$1 v80.01,35.57 | IC1.3 41.91,69.86 v48.26,63.51 | v77.47,66.05 v67.31,66.05 | 15.24,39.38 v22.86,31.76
VEE  (via drill 0.61)
  Top 0.762: R42.P$4 R42.P$5 | R39.P$4 R39.P$5 | TP3.P$1 17.78,54.62 R33.P$2 30.48,57.16 | C6.P$2 29.21,58.43 30.48,57.16 | 30.48,57.16 C5.P$2 | U2.VEE R10.P$1 | IC2.11 39.37,34.3 44.45,34.3 45.72,35.57 C17.P$2 52.07,31.76 v62.23,31.76 | v20.32,45.73 20.32,44.46 21.59,43.19 R26.P$1 | v20.32,17.79 20.32,22.87 24.13,26.68 R31.P$1
  Bottom 0.762: 20.32,2.55 40.64,2.55 43.18,5.09 49.53,5.09 R39.P$4 | R42.P$5 20.32,2.55 | C16.P$2 73.66,31.76 67.31,31.76 U2.VEE v62.23,31.76 | R31.P$1 24.13,34.3 | 24.13,34.3 21.59,36.84 R26.P$1 | R14.P$1 64.77,50.81 60.96,47 53.34,47 50.8,44.46 50.8,38.11 C17.P$2 | 24.13,34.3 34.29,34.3 IC2.11 | TP3.P$1 20.32,49.54 v20.32,45.73 | 20.32,2.55 v20.32,17.79

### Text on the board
tPlace: Karplus Strong | Copyright 2010 Les Hall | www.electro-music.com | VCO | VCF | FB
